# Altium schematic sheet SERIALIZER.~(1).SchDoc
size 431 x 279 mm; Date: Not shown in title block; ApprovedBy: Not shown in title block; CheckedBy: Not shown in title block; Author: Not shown in title block; CompanyName: Not shown in title block; DrawnBy: G. Fiolic; Engineer: Not shown in title block; Organization: Not shown in title block; Address1: Not shown in title block; Address2: Not shown in title block; Address3: Not shown in title block; Address4: Not shown in title block; DocumentNumber: 4; Revision: Use project parameter SCH_Rev; SheetNumber: 4; SheetTotal: 6; PageSetup: Record=PageOptions|CenterHorizontal=True|CenterVertical=True|PrintScale=1.00|XCorrection=1.00|YCorrection=1.00|PrintKind=0|BorderSize=5000000|LeftOffset=0|BottomOffset=0|Orientation=2|PaperLength=1000|PaperWidth=1000|Scale=100|PaperSource=15|PrintQuality=600|MediaType=1|DitherType=10|PaperKind=Letter|PrintScaleMode=1
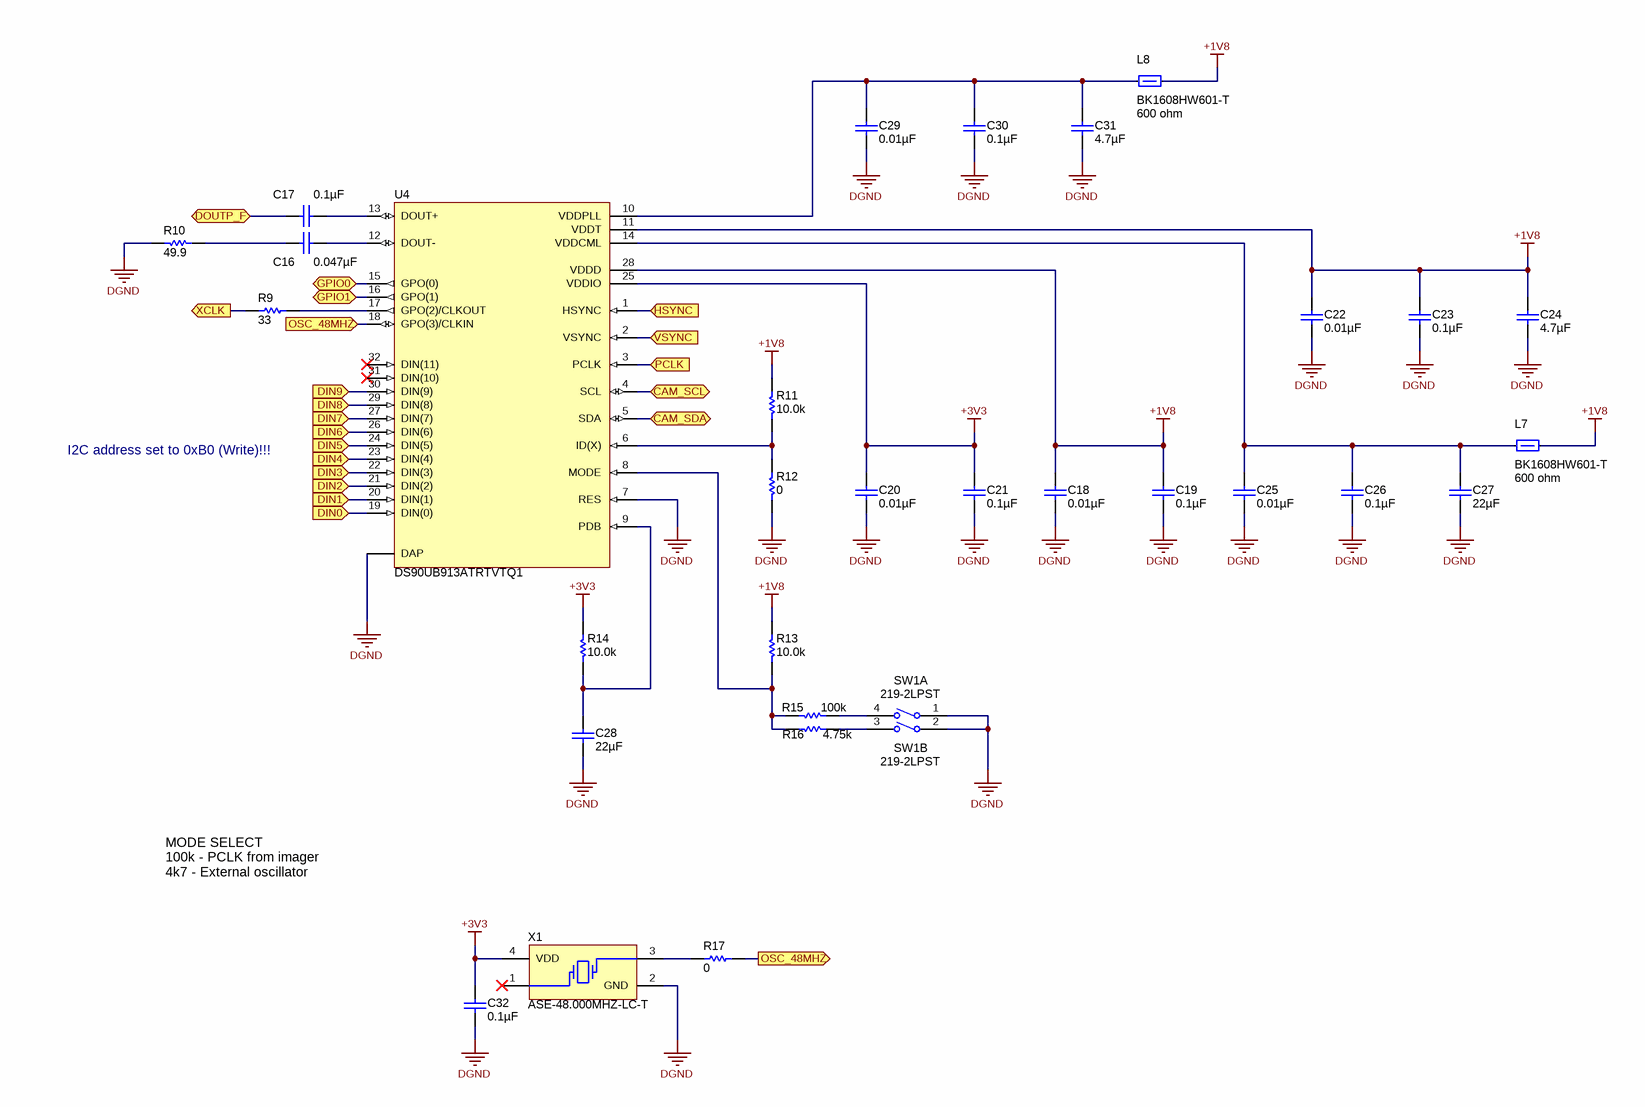
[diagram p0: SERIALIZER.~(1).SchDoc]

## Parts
C16  value 0.047µF  [0402L]  (hidden comment: CGA2B3X7R1H473K050BB)
C17  ValueDisplayed: 0.1µF  [0402L]  (hidden comment: C1005X7R1H104K050BB)
C18  ValueDisplayed: 0.01µF  [0402L]  (hidden comment: C1005X7R1C103K)
C19  ValueDisplayed: 0.1µF  [0402L]  (hidden comment: GRM155R71C104KA88D)
C20  ValueDisplayed: 0.01µF  [0402L]  (hidden comment: C1005X7R1C103K)
C21  ValueDisplayed: 0.1µF  [0402L]  (hidden comment: GRM155R71C104KA88D)
C22  ValueDisplayed: 0.01µF  [0402L]  (hidden comment: C1005X7R1C103K)
C23  ValueDisplayed: 0.1µF  [0402L]  (hidden comment: GRM155R71C104KA88D)
C24  ValueDisplayed: 4.7µF  [0805]  (hidden comment: GRM21BR71C475KA73L)
C25  ValueDisplayed: 0.01µF  [0402L]  (hidden comment: C1005X7R1C103K)
C26  ValueDisplayed: 0.1µF  [0402L]  (hidden comment: GRM155R71C104KA88D)
C27  ValueDisplayed: 22µF  [0805]  (hidden comment: C2012X5R1C226K125AC)
C28  ValueDisplayed: 22µF  [0805]  (hidden comment: C2012X5R1C226K125AC)
C29  ValueDisplayed: 0.01µF  [0402L]  (hidden comment: C1005X7R1C103K)
C30  ValueDisplayed: 0.1µF  [0402L]  (hidden comment: GRM155R71C104KA88D)
C31  ValueDisplayed: 4.7µF  [0805]  (hidden comment: GRM21BR71C475KA73L)
C32  ValueDisplayed: 0.1µF  [0402L]  (hidden comment: GRM155R71C104KA88D)
L7  BK1608HW601-T  value 600 ohm  [0603]
L8  value 600 ohm  [0603L]  (hidden comment: BK1608HW601-T)
R9  value 33  [0402L]  (hidden comment: CRCW040233R0JNED)
R10  value 49.9  [0402L]  (hidden comment: CRCW040249R9FKED)
R11  value 10.0k  [0402L]  (hidden comment: CRCW040210K0FKED)
R12  value 0  [0402L]  (hidden comment: CRCW04020000Z0ED)
R13  value 10.0k  [0402L]  (hidden comment: CRCW040210K0FKED)
R14  value 10.0k  [0402L]  (hidden comment: CRCW040210K0FKED)
R15  value 100k  [0402L]  (hidden comment: CRCW0402100KFKED)
R16  value 4.75k  [0402L]  (hidden comment: CRCW04024K75FKED)
R17  value 0  [0402L]  (hidden comment: CRCW04020000Z0ED)
SW1  219-2LPST  [SW_219-2LPST]  (parts A,B of 2)
U4  DS90UB913ATRTVTQ1  [RTV0032A]
X1  ASE-48.000MHZ-LC-T  [ASE-48.000MHZ-LC-T]

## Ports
CAM_SCL, CAM_SDA, DIN0, DIN1, DIN2, DIN3, DIN4, DIN5, DIN6, DIN7, DIN8, DIN9, DOUTP_F, GPIO0, GPIO1, HSYNC, OSC_48MHZ, PCLK, VSYNC, XCLK

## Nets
+1V8: C18.1 C19.1 C22.1 C23.1 C24.1 L7.2 L8.2 R11.1 R13.1 U4.11(VDDT) U4.28(VDDD)
+3V3: C20.1 C21.1 C32.1 R14.1 U4.25(VDDIO) X1.4(VDD)
DGND: C18.2 C19.2 C20.2 C21.2 C22.2 C23.2 C24.2 C25.2 C26.2 C27.2 C28.2 C29.2 C30.2 C31.2 C32.2 R10.2 R12.2 SW1.1(1A) SW1.2(2A) U4.7(RES) U4.33(DAP) X1.2(GND)
CAM_SCL: U4.4(SCL) ; port CAM_SCL
CAM_SDA: U4.5(SDA) ; port CAM_SDA
DIN0: U4.19(DIN(0)) ; port DIN0
DIN1: U4.20(DIN(1)) ; port DIN1
DIN2: U4.21(DIN(2)) ; port DIN2
DIN3: U4.22(DIN(3)) ; port DIN3
DIN4: U4.23(DIN(4)) ; port DIN4
DIN5: U4.24(DIN(5)) ; port DIN5
DIN6: U4.26(DIN(6)) ; port DIN6
DIN7: U4.27(DIN(7)) ; port DIN7
DIN8: U4.29(DIN(8)) ; port DIN8
DIN9: U4.30(DIN(9)) ; port DIN9
DOUTP_F: C17.1 ; port DOUTP_F
GPIO0: U4.15(GPO(0)) ; port GPIO0
GPIO1: U4.16(GPO(1)) ; port GPIO1
HSYNC: U4.1(HSYNC) ; port HSYNC
OSC_48MHZ: R17.1 U4.18(GPO(3)/CLKIN) ; port OSC_48MHZ
PCLK: U4.3(PCLK) ; port PCLK
VSYNC: U4.2(VSYNC) ; port VSYNC
XCLK: R9.1 ; port XCLK
NetC16_1: C16.1 R10.1
NetC16_2: C16.2 U4.12(DOUT-)
NetC17_2: C17.2 U4.13(DOUT+)
NetC25_1: C25.1 C26.1 C27.1 L7.1 U4.14(VDDCML)
NetC28_1: C28.1 R14.2 U4.9(PDB)
NetC29_1: C29.1 C30.1 C31.1 L8.1 U4.10(VDDPLL)
NetR9_2: R9.2 U4.17(GPO(2)/CLKOUT)
NetR11_2: R11.2 R12.1 U4.6(ID(X))
NetR13_2: R13.2 R15.2 R16.1 U4.8(MODE)
NetR15_1: R15.1 SW1.4(1B)
NetR16_2: R16.2 SW1.3(2B)
NetR17_2: R17.2 X1.3

Not connected (* = marked no-connect by the designer): U4 31(DIN(10))* 32(DIN(11))*; X1 1*

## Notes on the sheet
- I2C address set to 0xB0 (Write)!!!
- MODE SELECT
  100k - PCLK from imager
  4k7 - External oscillator

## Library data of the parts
C16 = Capacitor: CAP, CERM, 0.047uF, 50V, X7R, 10%, 0402; Manufacturer: TDK Corporation; Polarized: N; U/M: EA
C17 = C1005X7R1H104K050BB: CAP, CERM, 0.1uF, 50V, +/-10%, X7R, 0402; Manufacturer: TDK; Polarized: N; CompType: Capacitor; U/M: EA; Cap_F: 0.0000001; Tolerance_%: 10; Value1: Unknown; VDC_V: 50; TaMin_C: -55; TaMax_C: 125; Cap_Case: 0402
C18 C20 C22 C25 C29 = C1005X7R1C103K: CAP, CERM, 0.01uF, 16V, +/-10%, X7R, 0402; Manufacturer: TDK; Polarized: N; CompType: Capacitor; U/M: EA; Cap_F: 0.00000001; Tolerance_%: 10; ESR_Ohm: 0.0623; Value1: 0.0623 ohm; VDC_V: 16; TaMin_C: -55; TaMax_C: 125; Cap_Case: 0402
C19 C21 C23 C26 C30 C32 = GRM155R71C104KA88D: CAP, CERM, 0.1uF, 16V, +/-10%, X7R, 0402; Manufacturer: MuRata; Polarized: N; CompType: Capacitor; U/M: EA; Cap_F: 0.0000001; Tolerance_%: 10; Value1: Unknown; VDC_V: 16; TaMin_C: -55; TaMax_C: 125; Cap_Case: 0402
C24 C31 = GRM21BR71C475KA73L: CAP, CERM, 4.7uF, 16V, +/-10%, X7R, 0805; Manufacturer: MuRata; Polarized: N; CompType: Capacitor; U/M: EA; Cap_F: 0.0000047; Tolerance_%: 10; ESR_Ohm: 0.006; Value1: 0.006 ohm; VDC_V: 16; TaMin_C: -55; TaMax_C: 125
C27 C28 = C2012X5R1C226K125AC: CAP, CERM, 22uF, 16V, +/-10%, X5R, 0805; Manufacturer: TDK; Polarized: N; CompType: Capacitor; U/M: EA; Cap_F: 0.000022; Tolerance_%: 10; Value1: Unknown; VDC_V: 16; TaMin_C: -55; TaMax_C: 85
L7 L8 = Ferrite_Bead: 300mA Ferrite Bead, 600 ohm @ 100MHz; Manufacturer: Taiyo Yuden; U/M: EA
R9 = CRCW040233R0JNED: RES, 33 ohm, 5%, 0.063W, 0402; Manufacturer: Vishay-Dale; CompType: Resistor; Value_Code: 33R0; Tolerance_%: 5; Power_W: 0.063; VDC_V: 50; TempCo: 200 ppm/C; EIA_Code: E24; U/M: EA
R10 = CRCW040249R9FKED: RES, 49.9 ohm, 1%, 0.063W, 0402; Manufacturer: Vishay-Dale; CompType: Resistor; Value_Code: 49R9; Tolerance_%: 1; Power_W: 0.063; VDC_V: 50; TempCo: 100 ppm/C; EIA_Code: E96; U/M: EA
R11 R13 R14 = CRCW040210K0FKED: RES, 10.0k ohm, 1%, 0.063W, 0402; Manufacturer: Vishay-Dale; CompType: Resistor; Res_ohm: 10000; Value_Code: 10k0; Tolerance_%: 1; Power_W: 0.063; VDC_V: 50; TempCo: 100 ppm/C; EIA_Code: E96; U/M: EA
R12 R17 = CRCW04020000Z0ED: RES, 0 ohm, 5%, 0.063W, 0402; Manufacturer: Vishay-Dale; CompType: Resistor; Value_Code: 0000; Tolerance_%: 5; Power_W: 0.063; VDC_V: 50; TempCo: 200 ppm/C; EIA_Code: E24; U/M: EA
R15 = CRCW0402100KFKED: RES, 100k ohm, 1%, 0.063W, 0402; Manufacturer: Vishay-Dale; CompType: Resistor; Res_ohm: 100000; Tolerance_%: 1; Power_W: 0.063; VDC_V: 50; TempCo: 100 ppm/C; EIA_Code: E96; U/M: EA
R16 = CRCW04024K75FKED: RES, 4.75k ohm, 1%, 0.063W, 0402; Manufacturer: Vishay-Dale; CompType: Resistor; Res_ohm: 4750; Value_Code: 4k75; Tolerance_%: 1; Power_W: 0.063; VDC_V: 50; TempCo: 100 ppm/C; EIA_Code: E96; U/M: EA
SW1 = 219-2LPST: Switch, Slide, SPST 2 poles, SMT; Manufacturer: CTS Electrocomponents; SymbolCreator: a0413446/a0412235; VDC_V: 20; SwitchFunction: Off-On; PositionCount: 2; CurrentRating_mA: 100
U4 = DS90UB913ATRTVTQ1: DS90UB913A-Q1/DS90UB914A-Q1 25 to 100 MHz 10/20-Bit FPD-Link III Serializer and Deserializer, RTV0032A; Alternate Manufacturer: None; Manufacturer: Texas Instruments; SymbolCreator: x0208325; CompType: IC; U/M: EA
X1 = ASE-48.000MHZ-LC-T: OSC XO 48.00MHZ CMOS SMD; Manufacturer: Abracon Corporation; Frequency: 48MHz; Function: Tri-State (Output Enable); Voltage - Supply: 3.3V; Frequency Stability: ±50ppm; Current - Supply (Max): 19mA; Current - Supply (Disable) (Max): 10µA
